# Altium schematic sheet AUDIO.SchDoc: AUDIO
size A4; Date: Not used; ApprovedBy: Not used; CheckedBy: Not used; Author: Not used; CompanyName: STMicroelectronics; DrawnBy: Not used; Engineer: Not used; Organization: Not used; Address1: Not used; Address2: Not used; Address3: Not used; Address4: Not used; DocumentNumber: 11; Revision: Not used; SheetNumber: 11; SheetTotal: 16
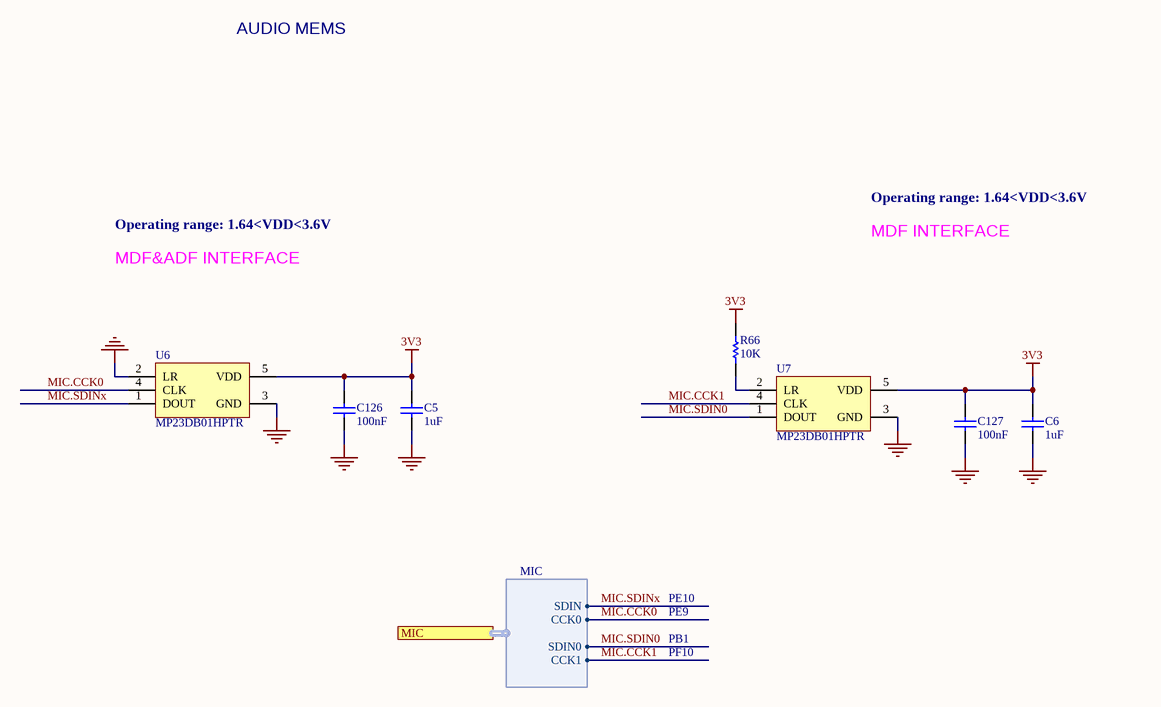
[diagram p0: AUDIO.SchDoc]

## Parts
C5  value 1uF  [C0603]
C6  value 1uF  [C0603]
C126  value 100nF  [C0402]
C127  value 100nF  [C0402]
R66  value 10K  [R0402]  (hidden comment: Resistor)
U6  value MP23DB01HPTR  [MIC_STM_MP23DB01MMTR]  (hidden comment: MP23DB01MMTR)
U7  value MP23DB01HPTR  [MIC_STM_MP23DB01MMTR]  (hidden comment: MP23DB01MMTR)

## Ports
MIC (harness MIC)

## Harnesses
MIC: SDIN, CCK0, SDIN0, CCK1

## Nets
3V3: C5.1 C6.1 C126.1 C127.1 R66.2 U6.5(VDD) U7.5(VDD)
GND: C5.2 C6.2 C126.2 C127.2 U6.2(LR) U6.3(GND) U7.3(GND)
MIC.CCK0: U6.4(CLK) ; port MIC.CCK0
MIC.CCK1: U7.4(CLK) ; port MIC.CCK1
MIC.SDIN0: U7.1(DOUT) ; port MIC.SDIN0
MIC.SDINx: U6.1(DOUT) ; port MIC.SDIN
NetR66_1: R66.1 U7.2(LR)

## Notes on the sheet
- AUDIO MEMS
- Operating range: 1.64<VDD<3.6V
- MDF&ADF INTERFACE
- MDF INTERFACE
- PE9
- PE10
- PB1
- PF10

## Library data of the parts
C5 C6 = MCD-00010: Capacitor, MLCC, 1uF, 16V, X5R, 10%, 0603, T=0,8mm; Manufacturer_Part_Number: CC0603KRX5R7BB105; Manufacturer: YAGEO; Provided_By: Subcon; Initial_Board_Reference: MB1274
C126 C127 = MCD-00006: Capacitor, MLCC, 100nF, 16V, X7R, 10%, 0402, T=0.5mm; Manufacturer_Part_Number: CC0402KRX7R7BB104; Manufacturer: YAGEO; Provided_By: Subcon; Initial_Board_Reference: MB1274
R66 = MCD-00053: Resistor,10K,0402,1%,1/16W; Manufacturer_Part_Number: RC0402FR-0710KL; Manufacturer: YAGEO; BMS_Part_Number: 9131590; ECCN_US: EAR99; ECCN_EU: NEC; Provided_By: SUBCO
U6 U7 = MCD-02122: MEMS sensors , omnidirectionnal digital microphone; Part_Type: IC; Manufacturer: STMICROELECTRONICS; ECCN_US: EAR99; ECCN_EU: NEC; Provided_By: SUBCO with ST control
